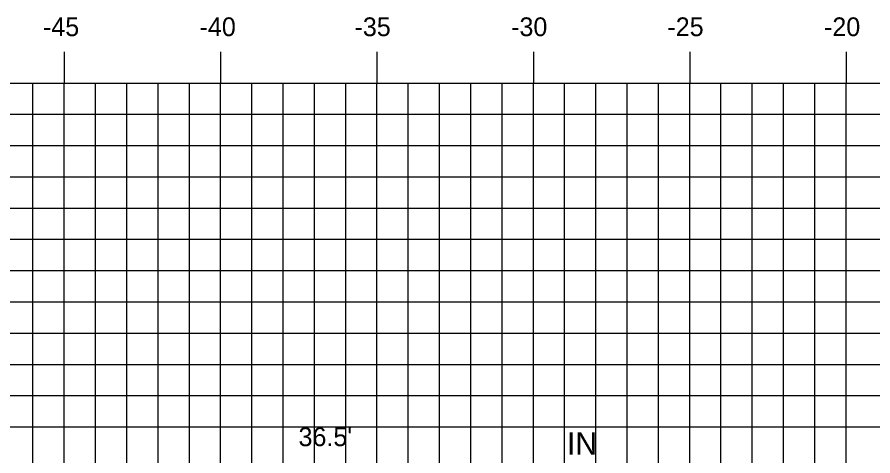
# Model space of a CAD drawing. Extents: x 1723764 to 1723936, y 458501 to 458611.
# Drawn here: x 1723801.03 to 1723828.4, y 458558.32 to 458572.36 of the extents above; entities that cross this region are included whole.
import ezdxf

# ---------------------------------------------------------------- set-up
doc = ezdxf.new("R2010")
doc.units = 0
for name, color, linetype in [('ANNOTATION', 7, 'Continuous'), ('D_Text_Standard', 7, 'Continuous'), ('H_V ANNOTATION', 7, 'Continuous'), ('MAJOR', 7, 'Continuous'), ('MINOR', 7, 'Continuous')]:
    doc.layers.add(name, color=color, linetype=linetype)

msp = doc.modelspace()

# ---------------------------------------------------------------- linework, layer by layer
at = {"layer": 'MAJOR'}
for p, q in [((1723802.542, 458571.256), (1723802.542, 458570.254)), ((1723807.542, 458571.256), (1723807.542, 458570.254)), ((1723812.542, 458571.256), (1723812.542, 458570.254)), ((1723817.542, 458571.256), (1723817.542, 458570.254)), ((1723822.542, 458571.256), (1723822.542, 458570.254)), ((1723827.542, 458571.256), (1723827.542, 458570.254)), ((1723777.542, 458570.254), (1723917.542, 458570.254)), ((1723777.542, 458570.254), (1723917.542, 458570.254)), ((1723802.542, 458545.254), (1723802.542, 458570.254)), ((1723807.542, 458545.254), (1723807.542, 458570.254)), ((1723812.542, 458545.254), (1723812.542, 458570.254)), ((1723817.542, 458545.254), (1723817.542, 458570.254)), ((1723822.542, 458545.254), (1723822.542, 458570.254)), ((1723827.542, 458545.254), (1723827.542, 458570.254)), ((1723777.542, 458565.254), (1723917.542, 458565.254)), ((1723777.542, 458560.254), (1723917.542, 458560.254))]:
    msp.add_line(p, q, dxfattribs=at)
at = {"layer": 'MINOR'}
for p, q in [((1723801.542, 458545.254), (1723801.542, 458570.254)), ((1723803.542, 458545.254), (1723803.542, 458570.254)), ((1723804.542, 458545.254), (1723804.542, 458570.254)), ((1723805.542, 458545.254), (1723805.542, 458570.254)), ((1723806.542, 458545.254), (1723806.542, 458570.254)), ((1723808.542, 458545.254), (1723808.542, 458570.254)), ((1723809.542, 458545.254), (1723809.542, 458570.254)), ((1723810.542, 458545.254), (1723810.542, 458570.254)), ((1723811.542, 458545.254), (1723811.542, 458570.254)), ((1723813.542, 458545.254), (1723813.542, 458570.254)), ((1723814.542, 458545.254), (1723814.542, 458570.254)), ((1723815.542, 458545.254), (1723815.542, 458570.254)), ((1723816.542, 458545.254), (1723816.542, 458570.254)), ((1723818.542, 458545.254), (1723818.542, 458570.254)), ((1723819.542, 458545.254), (1723819.542, 458570.254)), ((1723820.542, 458545.254), (1723820.542, 458570.254)), ((1723821.542, 458545.254), (1723821.542, 458570.254)), ((1723823.542, 458545.254), (1723823.542, 458570.254)), ((1723824.542, 458545.254), (1723824.542, 458570.254)), ((1723825.542, 458545.254), (1723825.542, 458570.254)), ((1723826.542, 458545.254), (1723826.542, 458570.254)), ((1723777.542, 458569.254), (1723917.542, 458569.254)), ((1723777.542, 458568.254), (1723917.542, 458568.254)), ((1723777.542, 458567.254), (1723917.542, 458567.254)), ((1723777.542, 458566.254), (1723917.542, 458566.254)), ((1723777.542, 458564.254), (1723917.542, 458564.254)), ((1723777.542, 458563.254), (1723917.542, 458563.254)), ((1723777.542, 458562.254), (1723917.542, 458562.254)), ((1723777.542, 458561.254), (1723917.542, 458561.254)), ((1723777.542, 458559.254), (1723917.542, 458559.254))]:
    msp.add_line(p, q, dxfattribs=at)

# ---------------------------------------------------------------- texts
at = {"layer": 'ANNOTATION'}
msp.add_text('IN', height=0.72, dxfattribs=at).set_placement((1723818.616, 458558.362))
at = {"layer": 'D_Text_Standard'}
msp.add_text("36.5'", height=0.6, dxfattribs=at).set_placement((1723810.032, 458558.636))
at = {"layer": 'H_V ANNOTATION'}
for s, p in [('-40', (1723806.868, 458571.754)), ('-35', (1723811.822, 458571.754)), ('-30', (1723816.83, 458571.754)), ('-25', (1723821.827, 458571.754)), ('-20', (1723826.835, 458571.754)), ('-45', (1723801.86, 458571.754))]:
    msp.add_text(s, height=0.6, dxfattribs=at).set_placement(p)

doc.saveas('drawing.dxf')
